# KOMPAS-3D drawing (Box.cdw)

Views: View 1, Isometric YZX
Referenced files in D:\Documents and Settings\kashirsky\Рабочий стол\My sample\: skrzynia1.a3d
Referenced files in H:\00_Work\Webinars\09_06_10_BOM\My sample\: Base plate.a3d, Side plate.a3d, Front_plate.a3d, Top_plate.a3d, Base plate.m3d, rail1.m3d, Side plate.m3d, rail2.m3d, Front_plate.m3d, rail3.m3d, Top_plate.m3d, rail4.m3d, skrzynia1.a3d
Referenced files: Box.cdw
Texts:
  Skrzynia
  Drawing Annotation
  Dimension Texts
  Surface Finish
  Leader #1
  Leader #2
  Leader #3
  Shape Deviations and Datum
  Table Header
  Table Cell
  Cut/Section Line
  Direction Arrow
  Modification Symbol
  Brace
  Node point number
  Mark of coordination axis
  VRCB
  Leader Text
  Node point designation
  Mark/Reference designation with leader
  Mark/reference designation on line
  Mark/Reference designation without leader
  System Layer
  System View
  Text of my assembly
  Plate 00
  Wood (15% moisture content)
  Plate of side
  Plate 03
  Plate 04
  Specifications
  Unspecified Surface Finish
  BOM table name
  Base plate
  Plate 01
  Rail of BP
  Rail 01
  Side plate
  Plate 02
  rail2
  Rail 02
  Front plate
  Rail
  Rail 03
  Top plate
  Rail 04
Dimensions and other numbers on the sheet: 0000; 7; 2; 4; 1; 114,24; 55,0694; 49,6608; 62,684; 1:1; 0000-; 386,38; 0; 3; 5; 6; 8; 9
